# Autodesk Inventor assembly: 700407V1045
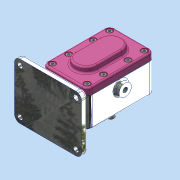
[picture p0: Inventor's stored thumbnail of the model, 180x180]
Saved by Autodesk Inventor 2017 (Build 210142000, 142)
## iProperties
Part Number: 700407V1045
Material: 일반
Document SubType Name: Assembly
Designer: MRC
Author: MRC
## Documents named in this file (11)
- C:\Users\MRC\Desktop\700407V1045\700407V1045.iam
- C:\Users\MRC\Desktop\700407V1045\Ű 6 x 6 x 18.ipt
- C:\Users\MRC\Desktop\700407V1045\개스킷.ipt
- C:\Users\MRC\Desktop\700407V1045\메인축.ipt
- C:\Users\MRC\Desktop\700407V1045\베어링부시.ipt
- C:\Users\MRC\Desktop\700407V1045\본체.ipt
- C:\Users\MRC\Desktop\700407V1045\볼트 M5.ipt
- C:\Users\MRC\Desktop\700407V1045\서브축.ipt
- C:\Users\MRC\Desktop\700407V1045\스퍼기어.ipt
- C:\Users\MRC\Desktop\700407V1045\오일 실 16 28 7.ipt
- C:\Users\MRC\Desktop\700407V1045\커버.ipt
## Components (3 placed, 2 different names)
1. Ű 6 x 6 x 18:1
2. 개스킷:1
3. Ű 6 x 6 x 18:2
